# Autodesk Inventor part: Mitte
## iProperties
Created: 2004-10
Part Number: Mitte
Document SubType Name: Modeling
Designer: sahrens
Manufacturer: Standard
Standards Organization: Custom
Knatenlaenge_Wuerfel: 63,000 mm
Kantenlaenge_Einzelteil: 21,000 mm
Durchmesser: 5,000 mm
Überstand: 7,000 mm
Author: sahrens
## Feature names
1. Drehung1 [Revolution]
2. Drehung2 [Revolution]
3. Drehung3 [Revolution]
